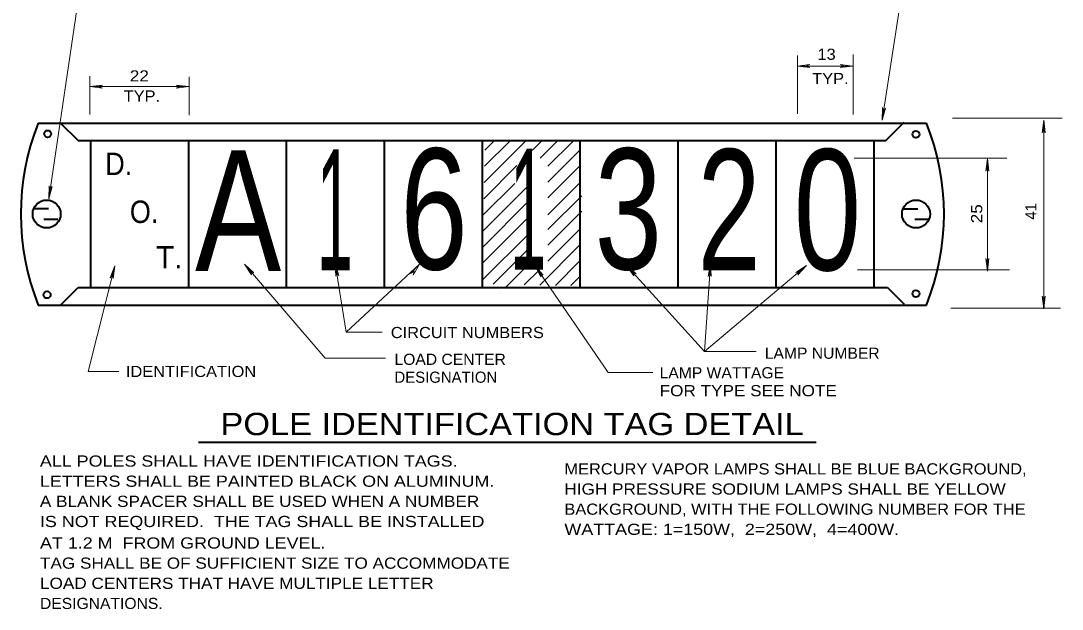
# Model space of a CAD drawing. Extents: x 312583 to 312854, y 144418 to 144597.
# Drawn here: x 312690.2 to 312761.2, y 144460.4 to 144500.4 of the extents above; entities that cross this region are included whole.
import ezdxf
from ezdxf.enums import TextEntityAlignment as Align

# ---------------------------------------------------------------- set-up
doc = ezdxf.new("R2010")
doc.units = 0
doc.header["$LTSCALE"] = 0.3
doc.layers.add('1', color=7, linetype='Continuous', lineweight=35)

msp = doc.modelspace()

# ---------------------------------------------------------------- linework, layer by layer
at = {"layer": '1', "lineweight": 13}
for p, q in [((312694.401, 144503.7339), (312692.1135, 144488.3162)), ((312743.1324, 144494.0959), (312743.1324, 144498.0609)), ((312746.922, 144494.0426), (312746.922, 144498.1448)), ((312743.1095, 144497.3518), (312743.9711, 144497.4586)), ((312743.1095, 144497.3518), (312746.9067, 144497.3518)), ((312743.1095, 144497.3518), (312743.9711, 144497.245)), ((312743.9711, 144497.4586), (312743.6966, 144497.3518)), ((312743.9711, 144497.245), (312743.6966, 144497.3518)), ((312746.0451, 144497.4586), (312746.3196, 144497.3518)), ((312746.9067, 144497.3518), (312746.0451, 144497.4586)), ((312746.0451, 144497.245), (312746.3196, 144497.3518)), ((312746.9067, 144497.3518), (312746.0451, 144497.245)), ((312694.9119, 144494.0578), (312694.9119, 144496.6656)), ((312701.6753, 144494.012), (312701.6753, 144496.6122)), ((312694.9195, 144495.9488), (312695.7811, 144496.0556)), ((312694.9195, 144495.9488), (312701.6676, 144495.9488)), ((312694.9195, 144495.9488), (312695.7811, 144495.842)), ((312695.7811, 144496.0556), (312695.5066, 144495.9488)), ((312695.7811, 144495.842), (312695.5066, 144495.9488)), ((312700.806, 144496.0556), (312701.0805, 144495.9488)), ((312701.6676, 144495.9488), (312700.806, 144496.0556)), ((312700.806, 144495.842), (312701.0805, 144495.9488)), ((312701.6676, 144495.9488), (312700.806, 144495.842)), ((312748.8969, 144493.6537), (312748.9197, 144494.5229)), ((312748.8969, 144493.6537), (312749.1333, 144494.4848)), ((312748.9197, 144494.5229), (312748.9884, 144494.2332)), ((312749.1333, 144494.4848), (312748.9884, 144494.2332)), ((312759.915, 144493.6689), (312759.8083, 144492.8073)), ((312759.8083, 144492.8073), (312759.915, 144493.0818)), ((312759.915, 144480.8056), (312759.915, 144493.6689)), ((312759.915, 144493.6689), (312760.0217, 144492.8073)), ((312760.0217, 144492.8073), (312759.915, 144493.0818)), ((312721.7824, 144489.4142), (312724.5807, 144492.2202)), ((312721.8053, 144490.5198), (312723.5056, 144492.2202)), ((312721.8281, 144491.6178), (312722.4229, 144492.2202)), ((312724.535, 144491.0917), (312725.6635, 144492.2202)), ((312725.5949, 144491.0764), (312726.7386, 144492.2202)), ((312726.121, 144490.5198), (312727.8214, 144492.2202)), ((312726.121, 144489.4447), (312728.2789, 144491.6026)), ((312756.0796, 144491.0536), (312755.9729, 144490.1919)), ((312756.0796, 144483.3828), (312756.0796, 144491.0536)), ((312756.0796, 144491.0536), (312756.1864, 144490.1919)), ((312721.7595, 144488.3162), (312724.0165, 144490.5732)), ((312726.1286, 144488.3696), (312728.3323, 144490.5732)), ((312755.9729, 144490.1919), (312756.0796, 144490.4664)), ((312756.1864, 144490.1919), (312756.0796, 144490.4664)), ((312692.1135, 144488.3162), (312692.1364, 144489.1854)), ((312692.1135, 144488.3162), (312692.3423, 144489.1549)), ((312692.1364, 144489.1854), (312692.1974, 144488.8957)), ((312692.3423, 144489.1549), (312692.1974, 144488.8957)), ((312721.7061, 144486.1049), (312724.7943, 144489.193)), ((312721.729, 144487.2106), (312723.8793, 144489.3608)), ((312726.1286, 144487.2182), (312728.3475, 144489.4294)), ((312721.6756, 144484.9993), (312724.7943, 144488.1179)), ((312726.1286, 144486.2193), (312728.4314, 144488.5144)), ((312726.1363, 144485.1518), (312728.439, 144487.4546)), ((312721.6527, 144483.9013), (312724.7866, 144487.0276)), ((312726.1363, 144484.0614), (312728.3551, 144486.2803)), ((312721.729, 144482.8262), (312724.779, 144485.8686)), ((312722.3924, 144482.483), (312724.7714, 144484.862)), ((312725.572, 144482.422), (312728.3627, 144485.2128)), ((312710.9473, 144477.4506), (312705.4573, 144483.8479)), ((312705.4573, 144483.8479), (312705.9376, 144483.1236)), ((312705.4573, 144483.8479), (312706.0977, 144483.2608)), ((312712.3731, 144479.2196), (312711.6411, 144483.9089)), ((312711.6411, 144483.9089), (312711.6716, 144483.0397)), ((312711.6411, 144483.9089), (312711.8775, 144483.0778)), ((312712.3731, 144479.2196), (312717.3751, 144483.8479)), ((312717.3751, 144483.8479), (312716.7651, 144483.2303)), ((312717.3751, 144483.8479), (312716.9405, 144483.1007)), ((312726.6395, 144482.4068), (312728.2941, 144484.069)), ((312736.796, 144477.908), (312737.2154, 144483.8784)), ((312737.2154, 144483.8784), (312737.0476, 144483.0244)), ((312737.2154, 144483.8784), (312737.2611, 144483.0092)), ((312755.9729, 144484.2444), (312756.0796, 144483.9699)), ((312756.0796, 144483.3828), (312755.9729, 144484.2444)), ((312756.1864, 144484.2444), (312756.0796, 144483.9699)), ((312756.0796, 144483.3828), (312756.1864, 144484.2444)), ((312694.8051, 144476.5356), (312696.6123, 144483.7412)), ((312696.6123, 144483.7412), (312696.2996, 144482.9329)), ((312696.2996, 144482.9329), (312696.4674, 144483.1693)), ((312696.5055, 144482.8796), (312696.4674, 144483.1693)), ((312696.6123, 144483.7412), (312696.5055, 144482.8796)), ((312705.9376, 144483.1236), (312705.8385, 144483.4057)), ((312706.0977, 144483.2608), (312705.8385, 144483.4057)), ((312711.6716, 144483.0397), (312711.7326, 144483.3294)), ((312711.8775, 144483.0778), (312711.7326, 144483.3294)), ((312716.7651, 144483.2303), (312717.0167, 144483.3828)), ((312716.9405, 144483.1007), (312717.0167, 144483.3828)), ((312723.193, 144482.2162), (312724.7714, 144483.7869)), ((312724.5197, 144482.4449), (312725.5491, 144483.4743)), ((312725.389, 144483.4743), (312725.6406, 144482.9939)), ((312730.2385, 144476.4746), (312725.4424, 144483.4743)), ((312725.4957, 144483.4743), (312725.816, 144483.1159)), ((312725.6406, 144482.9939), (312725.572, 144483.2837)), ((312725.816, 144483.1159), (312725.572, 144483.2837)), ((312736.796, 144477.908), (312731.489, 144483.764)), ((312731.489, 144483.764), (312731.9846, 144483.0549)), ((312731.489, 144483.764), (312732.1447, 144483.1998)), ((312731.9846, 144483.0549), (312731.8855, 144483.3294)), ((312732.1447, 144483.1998), (312731.8855, 144483.3294)), ((312736.796, 144477.908), (312743.75, 144483.764)), ((312737.0476, 144483.0244), (312737.1773, 144483.2913)), ((312737.2611, 144483.0092), (312737.1773, 144483.2913)), ((312743.75, 144483.764), (312743.0256, 144483.2913)), ((312743.0256, 144483.2913), (312743.3001, 144483.3828)), ((312743.75, 144483.764), (312743.1629, 144483.1312)), ((312743.1629, 144483.1312), (312743.3001, 144483.3828)), ((312727.6994, 144482.3916), (312728.3627, 144483.0626)), ((312722.9261, 144481.9493), (312722.9337, 144481.9569)), ((312759.8083, 144481.6672), (312759.915, 144481.3927)), ((312759.915, 144480.8056), (312759.8083, 144481.6672)), ((312760.0217, 144481.6672), (312759.915, 144481.3927)), ((312759.915, 144480.8056), (312760.0217, 144481.6672)), ((312712.3731, 144479.2196), (312714.836, 144479.2196)), ((312710.9473, 144477.4506), (312715.0647, 144477.4506)), ((312736.796, 144477.908), (312740.3187, 144477.908)), ((312694.8051, 144476.5356), (312696.902, 144476.5356)), ((312730.2385, 144476.4746), (312733.2809, 144476.4746))]:
    msp.add_line(p, q, dxfattribs=at)
at = {"layer": '1', "lineweight": 40}
for p, q in [((312691.4044, 144493.463), (312751.9316, 144493.463)), ((312692.9217, 144493.4707), (312694.1113, 144492.2736)), ((312749.1561, 144492.2736), (312750.4143, 144493.5317)), ((312694.1113, 144492.2736), (312749.1561, 144492.2736)), ((312694.9805, 144482.2619), (312694.9805, 144492.2736)), ((312701.6524, 144482.2619), (312701.6524, 144492.2736)), ((312708.3243, 144482.2619), (312708.3243, 144492.2736)), ((312714.9961, 144482.2619), (312714.9961, 144492.2736)), ((312721.668, 144482.2619), (312721.668, 144492.2736)), ((312728.3399, 144482.2619), (312728.3399, 144492.2736)), ((312735.0117, 144482.2619), (312735.0117, 144492.2736)), ((312741.6836, 144482.2619), (312741.6836, 144492.2736)), ((312748.3555, 144482.2619), (312748.3555, 144492.2736)), ((312691.1451, 144487.6452), (312692.0983, 144487.6452)), ((312750.3837, 144487.6147), (312751.3369, 144487.6147)), ((312691.778, 144486.9284), (312692.7311, 144486.9284)), ((312751.1234, 144486.9284), (312752.0765, 144486.9284)), ((312692.9217, 144481.0648), (312694.1189, 144482.2619)), ((312694.1189, 144482.2619), (312749.2781, 144482.2619)), ((312749.2781, 144482.2619), (312750.4066, 144481.1258)), ((312691.4044, 144481.0724), (312751.9316, 144481.0724)), ((312702.3154, 144471.7318), (312744.4085, 144471.7318))]:
    msp.add_line(p, q, dxfattribs=at)
at = {"layer": '1', "lineweight": 13}
for points in [[(312743.0409, 144504.1076), (312750.5134, 144504.1076), (312748.8969, 144493.6537)], [(312753.7083, 144493.7986), (312754.2191, 144493.7986), (312761.1731, 144493.7986)], [(312746.9906, 144491.084), (312754.2191, 144491.084), (312757.3987, 144491.084)], [(312747.2194, 144483.459), (312754.2191, 144483.459), (312757.5741, 144483.459)], [(312753.5939, 144480.8589), (312754.2191, 144480.8589), (312761.0587, 144480.8589)]]:
    msp.add_lwpolyline(points, dxfattribs=at)
at = {"layer": '1', "lineweight": 40}
for centre, radius in [((312692.0372, 144492.7311), 0.2383), ((312751.2072, 144492.6929), 0.2383), ((312691.9763, 144487.2716), 0.9531), ((312751.2149, 144487.2716), 0.9531), ((312692.0068, 144481.7663), 0.2383), ((312751.2072, 144481.8426), 0.2383)]:
    msp.add_circle(centre, radius, dxfattribs=at)
for centre, start, end in [((312706.9432, 144487.2677), 158.26294, 201.73706), ((312736.3928, 144487.2677), 338.26294, 21.73706)]:
    msp.add_arc(centre, 16.7284, start, end, dxfattribs=at)

# ---------------------------------------------------------------- texts
at = {"layer": '1'}
for s, width, p in [('13 ', 1.1, (312744.4969, 144497.7724)), ('22 ', 1.15, (312697.6392, 144496.2986)), ('TYP.', 1.1, (312744.1364, 144496.1198)), ('TYP.', 1.1, (312697.2213, 144494.928)), ('CIRCUIT NUMBERS', 1.1, (312715.4229, 144478.8176)), ('LAMP NUMBER', 1.05, (312740.9091, 144477.4112)), ('LOAD CENTER', 1.05, (312715.675, 144476.9939)), ('IDENTIFICATION', 1.1, (312697.3731, 144476.168)), ('LAMP WATTAGE', 1.05, (312733.7427, 144476.0755)), ('FOR TYPE SEE NOTE', 1.15, (312733.7427, 144474.858)), ('ALL POLES SHALL HAVE IDENTIFICATION TAGS.', 1.2, (312691.5128, 144470.0644)), ('MERCURY VAPOR LAMPS SHALL BE BLUE BACKGROUND,', 1.1, (312727.2549, 144469.5307)), ('LETTERS SHALL BE PAINTED BLACK ON ALUMINUM. ', 1.2, (312691.5128, 144468.6919)), ('HIGH PRESSURE SODIUM LAMPS SHALL BE YELLOW', 1.15, (312727.2549, 144468.1582)), ('A BLANK SPACER SHALL BE USED WHEN A NUMBER', 1.15, (312691.5128, 144467.3194)), ('BACKGROUND, WITH THE FOLLOWING NUMBER FOR THE', 1.1, (312727.2549, 144466.7857)), ('IS NOT REQUIRED.  THE TAG SHALL BE INSTALLED', 1.2, (312691.5128, 144465.9469)), ('WATTAGE: 1=150W,  2=250W,  4=400W.', 1.2, (312727.2549, 144465.4132)), ('AT 1.2 M  FROM GROUND LEVEL.', 1.2, (312691.5204, 144464.4829)), ('TAG SHALL BE OF SUFFICIENT SIZE TO ACCOMMODATE', 1.15, (312691.5204, 144463.1104)), ('LOAD CENTERS THAT HAVE MULTIPLE LETTER', 1.15, (312691.5204, 144461.7379)), ('DESIGNATIONS.', 1.05, (312691.5204, 144460.3654))]:
    msp.add_text(s, height=0.76, dxfattribs=dict(at, width=width)).set_placement(p)
for s, height, width, p in [('A', 8.235, 0.8, (312705.0226, 144483.3828)), ('1', 8.235, 0.4, (312711.6106, 144483.4438)), ('6', 8.235, 0.75, (312718.3701, 144483.4972)), ('1', 8.235, 0.4, (312724.779, 144483.4819)), ('3', 8.235, 0.75, (312731.611, 144483.4972)), ('2', 8.235, 0.7, (312738.4772, 144483.4438)), ('0', 8.235, 0.75, (312745.1797, 144483.4438)), ('D.', 1.525, 0.9, (312696.8868, 144489.925)), ('O.', 1.525, 0.9, (312698.6139, 144486.6616)), ('POLE IDENTIFICATION TAG DETAIL', 1.52, 1.15, (312723.6891, 144472.2081))]:
    msp.add_text(s, height=height, dxfattribs=dict(at, width=width)).set_placement(p, align=Align.CENTER)
at = {"layer": '1', "width": 1.15}
msp.add_text('25 ', height=0.76, rotation=90, dxfattribs=at).set_placement((312755.7257, 144486.6403))
at = {"layer": '1'}
msp.add_text('41 ', height=0.76, rotation=90, dxfattribs=at).set_placement((312759.417, 144486.8881))
msp.add_text('T.', height=1.525, dxfattribs=at).set_placement((312700.3295, 144483.5658), align=Align.CENTER)
msp.add_text('DESIGNATION', height=0.76, dxfattribs=at).set_placement((312715.675, 144475.7764))

doc.saveas('drawing.dxf')
